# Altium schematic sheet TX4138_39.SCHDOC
size A; SheetNumber: 0; SheetTotal: 0
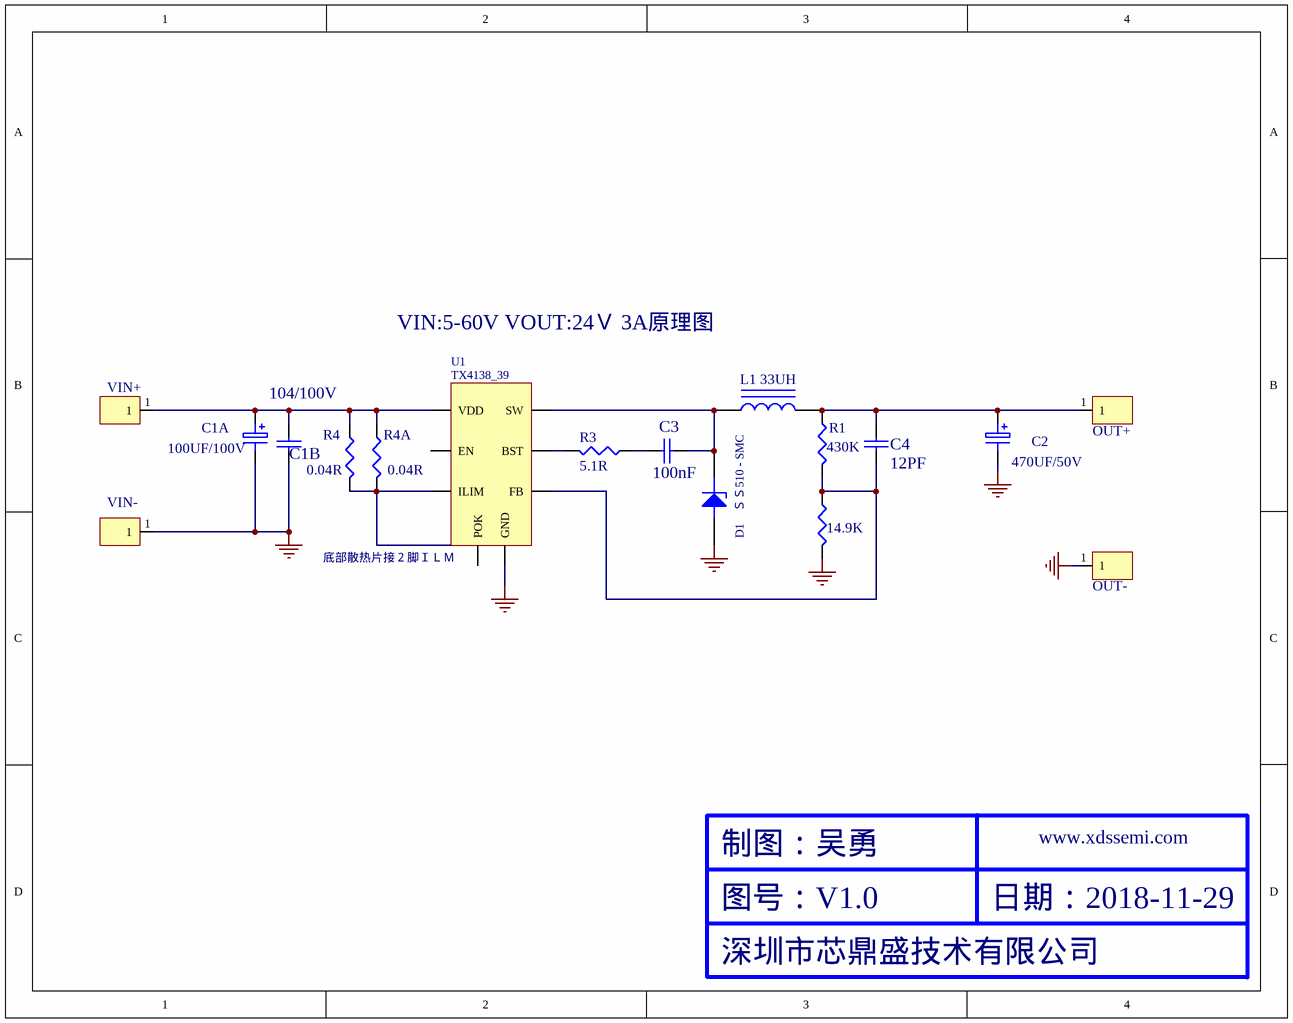
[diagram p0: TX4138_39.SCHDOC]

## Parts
(Parts that share a designator on the sheet are numbered #1, #2 ... from top to bottom, then left to right.)
?  VIN-  [pad]
A#1  VIN+  [pad]
A#2  OUT+  [pad]
A#3  OUT-  [pad]
C1A  100UF/100V  [C6.3*2.5]
C1B  104/100V
C2  470UF/50V  [C6.3*2.5]
C3  100nF
C4  12PF
D1_ＳＳ510_-_SMC  (no value)
L1_33UH  (no value)  [ls12*12]
R1  430K  [r1206]
R2  14.9K  [r1206]
R3  5.1R  [r1206]
R4  0.04R  [r1206]
R4A  0.04R  [r1206]
U1  TX4138_39

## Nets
GND: ?.1 A#3.1 C1A.2 C1B.2 C2.2 D1_ＳＳ510_-_SMC.1(A) R2.2 U1.?5(GND)
NetA#1_1: A#1.1 C1A.1 C1B.1 R4.1 R4A.1 U1.?1(VDD)
NetA#2_1: A#2.1 C2.1 C4.1 L1_33UH.1 R1.1
NetC3_1: C3.1 D1_ＳＳ510_-_SMC.2(K) L1_33UH.2 U1.?8(SW)
NetC3_2: C3.2 R3.1
NetC4_2: C4.2 R1.2 R2.1 U1.?6(FB)
NetR3_2: R3.2 U1.?7(BST)
NetR4_2: R4.2 R4A.2 U1.?3(ILIM)

Not connected (* = marked no-connect by the designer): U1 ?2(EN) ?4(POK)

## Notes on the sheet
- VIN:5-60V VOUT:24Ｖ 3A原理图
- 底部散热片接２脚ＩＬＭ
- 制图：吴勇
- 图号：V1.0
- 日期：2018-11-29
- www.xdssemi.com
- 深圳市芯鼎盛技术有限公司

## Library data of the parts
? A#1-A#3 = IN
C1A C2 = C
C1B C3 C4 = CAP: Capacitor
D1_ＳＳ510_-_SMC = ZENER1: Zener Diode
L1_33UH = INDUCTOR IRON
R1-R4 R4A = RES1
U1 = Component_1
